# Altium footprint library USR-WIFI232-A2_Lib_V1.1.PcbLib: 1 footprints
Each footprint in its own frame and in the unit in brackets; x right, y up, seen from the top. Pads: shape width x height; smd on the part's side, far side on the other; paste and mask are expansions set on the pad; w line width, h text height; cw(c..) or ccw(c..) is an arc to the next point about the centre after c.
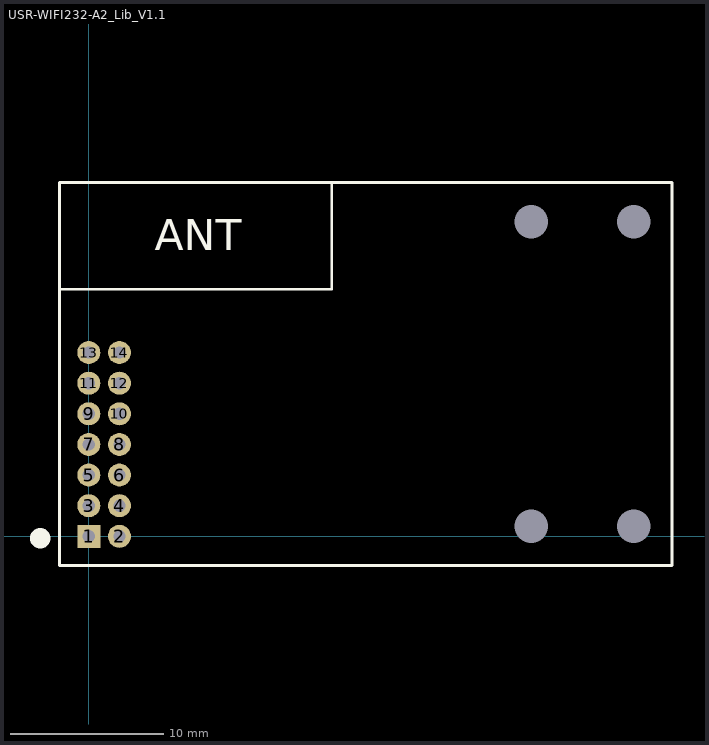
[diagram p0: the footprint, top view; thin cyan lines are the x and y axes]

## USR-WIFI232-A2_Lib_V1.1 [mm]
pads (18):
  round 0 hole 2.2: 0(28.89,0.65) 0(28.89,20.55) 0(35.6,0.65) 0(35.6,20.55)
  rect 1.5x1.5 hole 0.8: 1(0,0)
  round 1.5 hole 0.8: 2(2,0) 3(0,2) 4(2,2) 5(0,4) 6(2,4) 7(0,6) 8(2,6) 9(0,8) 10(2,8) 11(0,10) 12(2,10) 13(0,12) 14(2,12)
TopOverlay:
  circle w0.762: c-3.175,-0.127 r0.284
  lines w0.152: -1.9,16.145 15.875,16.145 15.875,23.1
  lines w0.203: -1.9,-1.9 38.1,-1.9 38.1,23.1 -1.9,23.1 -1.9,-1.9
  text "ANT" at 4.318,18.669 h2.03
